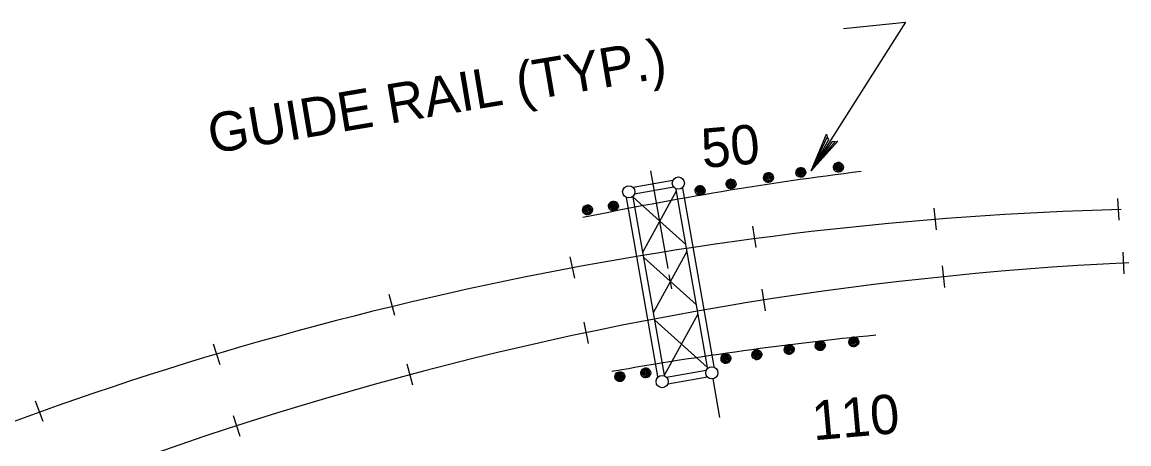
# Model space of a CAD drawing. Extents: x 36 to 2622, y -5330 to 219.
# Drawn here: x 593.7 to 678.2, y -4850.5 to -4818.3 of the extents above; entities that cross this region are included whole.
import ezdxf

# ---------------------------------------------------------------- set-up
doc = ezdxf.new("R2010")
doc.units = 0
doc.layers.add('2', color=7, linetype='Continuous')
doc.layers.add('3', color=7, linetype='Continuous')

# ---------------------------------------------------------------- blocks, each defined once
blk = doc.blocks.new('RARROW')
at = {"layer": '3'}
blk.add_lwpolyline([(-2.2695, 0.285), (-2.184875, 0.12075), (0, 0), (-2.2695, 0.285), (-2.38575, 0.384625), (0, 0), (-2.183125, -0.108), (-2.262875, -0.2705), (0, 0), (-2.38575, -0.379125), (-2.262875, -0.2705)], dxfattribs=at)

msp = doc.modelspace()

# ---------------------------------------------------------------- linework, layer by layer
at = {"layer": '2'}
for p, q in [((641.695, -4829.641), (643.005, -4837.09)), ((643.382, -4830.375), (640.364, -4830.908)), ((642.253, -4845.307), (639.846, -4831.665)), ((642.762, -4845.217), (640.368, -4831.631)), ((640.368, -4831.631), (644.385, -4835.257)), ((643.474, -4830.887), (640.449, -4831.421)), ((641.111, -4835.836), (643.663, -4831.161)), ((646.038, -4844.637), (643.644, -4831.053)), ((646.55, -4844.547), (644.156, -4830.962)), ((663.31, -4832.48), (663.481, -4834.13)), ((677.45, -4833.406), (677.366, -4831.75)), ((649.745, -4835.488), (649.49, -4833.851)), ((641.918, -4840.435), (644.474, -4835.763)), ((677.853, -4837.487), (677.77, -4835.831)), ((635.54, -4836.187), (635.883, -4837.81)), ((641.177, -4836.231), (645.194, -4839.855)), ((643.093, -4837.577), (643.278, -4838.636)), ((663.955, -4836.886), (664.126, -4838.536)), ((622.168, -4840.678), (621.742, -4839.074)), ((650.471, -4840.304), (650.216, -4838.667)), ((642.762, -4845.217), (645.319, -4840.545)), ((636.588, -4841.167), (636.931, -4842.79)), ((642.022, -4841.015), (646.038, -4844.637)), ((608.291, -4842.831), (608.801, -4844.408)), ((623.539, -4845.985), (623.113, -4844.381)), ((645.937, -4844.851), (642.914, -4845.386)), ((646.026, -4845.363), (643.005, -4845.898)), ((646.434, -4845.504), (646.95, -4848.437)), ((595.336, -4848.747), (594.745, -4847.198)), ((609.824, -4848.3), (610.334, -4849.877))]:
    msp.add_line(p, q, dxfattribs=at)
for points in [[(656.417, -4818.784), (661.157, -4818.291), (653.95, -4829.637)], [(656.03, -4829.356), (655.961, -4829.341), (655.965, -4829.293), (656.038, -4829.277), (656.09, -4829.312), (656.082, -4829.395), (656.007, -4829.437), (655.924, -4829.406), (655.88, -4829.327), (655.909, -4829.241), (656.005, -4829.198), (656.096, -4829.21), (656.154, -4829.306), (656.152, -4829.418), (656.036, -4829.512), (655.907, -4829.493), (655.822, -4829.393), (655.82, -4829.231), (655.934, -4829.135), (656.086, -4829.123), (656.182, -4829.2), (656.231, -4829.331), (656.229, -4829.447), (656.15, -4829.557), (656.028, -4829.599), (655.901, -4829.591), (655.797, -4829.505), (655.73, -4829.37), (655.745, -4829.258), (655.824, -4829.119), (655.971, -4829.054), (656.157, -4829.071), (656.265, -4829.166), (656.3, -4829.293), (656.319, -4829.453), (656.24, -4829.58), (656.094, -4829.659), (655.953, -4829.689), (655.845, -4829.678), (655.745, -4829.607), (655.68, -4829.497), (655.655, -4829.387), (655.662, -4829.277), (655.701, -4829.166), (655.776, -4829.075), (655.878, -4829.012), (655.988, -4828.977), (656.09, -4828.981), (656.19, -4829.01), (656.277, -4829.071), (656.348, -4829.156), (656.398, -4829.26), (656.408, -4829.383), (656.39, -4829.474), (656.34, -4829.574), (656.265, -4829.649), (656.159, -4829.713), (656.044, -4829.734), (655.951, -4829.73), (655.861, -4829.701), (655.793, -4829.651)], [(650.694, -4830.14), (650.625, -4830.125), (650.63, -4830.078), (650.702, -4830.061), (650.754, -4830.096), (650.746, -4830.179), (650.671, -4830.221), (650.588, -4830.19), (650.544, -4830.111), (650.573, -4830.025), (650.669, -4829.982), (650.76, -4829.994), (650.819, -4830.09), (650.817, -4830.202), (650.7, -4830.296), (650.571, -4830.277), (650.486, -4830.177), (650.484, -4830.015), (650.598, -4829.919), (650.75, -4829.907), (650.846, -4829.984), (650.896, -4830.115), (650.894, -4830.231), (650.815, -4830.342), (650.692, -4830.383), (650.565, -4830.375), (650.461, -4830.29), (650.394, -4830.155), (650.409, -4830.042), (650.488, -4829.903), (650.636, -4829.838), (650.821, -4829.855), (650.929, -4829.951), (650.964, -4830.078), (650.983, -4830.238), (650.904, -4830.364), (650.759, -4830.444), (650.617, -4830.473), (650.509, -4830.462), (650.409, -4830.392), (650.345, -4830.281), (650.32, -4830.171), (650.326, -4830.061), (650.365, -4829.951), (650.44, -4829.859), (650.542, -4829.797), (650.652, -4829.761), (650.754, -4829.766), (650.854, -4829.794), (650.942, -4829.855), (651.012, -4829.94), (651.062, -4830.044), (651.072, -4830.167), (651.054, -4830.258), (651.004, -4830.358), (650.929, -4830.433), (650.823, -4830.498), (650.708, -4830.519), (650.615, -4830.514), (650.525, -4830.485), (650.457, -4830.435)], [(653.161, -4829.749), (653.092, -4829.734), (653.097, -4829.686), (653.169, -4829.67), (653.221, -4829.705), (653.213, -4829.788), (653.138, -4829.83), (653.055, -4829.799), (653.011, -4829.72), (653.04, -4829.634), (653.136, -4829.591), (653.228, -4829.603), (653.286, -4829.699), (653.284, -4829.811), (653.167, -4829.905), (653.038, -4829.886), (652.953, -4829.786), (652.951, -4829.624), (653.065, -4829.528), (653.217, -4829.516), (653.313, -4829.593), (653.363, -4829.724), (653.361, -4829.84), (653.282, -4829.951), (653.159, -4829.992), (653.032, -4829.984), (652.928, -4829.899), (652.861, -4829.763), (652.876, -4829.651), (652.955, -4829.512), (653.103, -4829.447), (653.288, -4829.464), (653.396, -4829.56), (653.432, -4829.686), (653.45, -4829.847), (653.371, -4829.974), (653.226, -4830.052), (653.084, -4830.082), (652.976, -4830.071), (652.876, -4830.001), (652.812, -4829.89), (652.787, -4829.78), (652.793, -4829.67), (652.832, -4829.56), (652.907, -4829.468), (653.009, -4829.406), (653.12, -4829.37), (653.221, -4829.374), (653.321, -4829.404), (653.409, -4829.464), (653.479, -4829.549), (653.529, -4829.653), (653.54, -4829.776), (653.521, -4829.867), (653.471, -4829.967), (653.396, -4830.042), (653.29, -4830.107), (653.176, -4830.127), (653.082, -4830.123), (652.993, -4830.094), (652.924, -4830.044)], [(645.469, -4831.128), (645.4, -4831.113), (645.404, -4831.066), (645.477, -4831.049), (645.529, -4831.084), (645.52, -4831.168), (645.446, -4831.209), (645.362, -4831.178), (645.319, -4831.099), (645.348, -4831.014), (645.443, -4830.97), (645.535, -4830.982), (645.593, -4831.078), (645.591, -4831.19), (645.475, -4831.284), (645.346, -4831.265), (645.26, -4831.165), (645.258, -4831.003), (645.373, -4830.908), (645.525, -4830.895), (645.62, -4830.972), (645.67, -4831.103), (645.668, -4831.22), (645.589, -4831.33), (645.466, -4831.371), (645.34, -4831.363), (645.236, -4831.278), (645.169, -4831.142), (645.183, -4831.03), (645.263, -4830.891), (645.41, -4830.826), (645.595, -4830.843), (645.703, -4830.939), (645.739, -4831.066), (645.758, -4831.226), (645.679, -4831.353), (645.533, -4831.432), (645.392, -4831.461), (645.283, -4831.45), (645.183, -4831.38), (645.119, -4831.269), (645.094, -4831.159), (645.1, -4831.049), (645.14, -4830.939), (645.215, -4830.847), (645.317, -4830.785), (645.427, -4830.749), (645.529, -4830.753), (645.629, -4830.783), (645.716, -4830.843), (645.787, -4830.928), (645.837, -4831.032), (645.847, -4831.155), (645.828, -4831.247), (645.778, -4831.346), (645.703, -4831.421), (645.597, -4831.486), (645.483, -4831.507), (645.389, -4831.502), (645.3, -4831.473), (645.231, -4831.423)], [(647.836, -4830.633), (647.767, -4830.618), (647.771, -4830.57), (647.844, -4830.554), (647.896, -4830.589), (647.888, -4830.672), (647.813, -4830.714), (647.73, -4830.683), (647.686, -4830.604), (647.715, -4830.519), (647.811, -4830.475), (647.902, -4830.487), (647.961, -4830.583), (647.958, -4830.695), (647.842, -4830.789), (647.713, -4830.77), (647.628, -4830.67), (647.626, -4830.508), (647.74, -4830.412), (647.892, -4830.4), (647.988, -4830.477), (648.038, -4830.608), (648.036, -4830.724), (647.956, -4830.835), (647.834, -4830.876), (647.707, -4830.868), (647.603, -4830.783), (647.536, -4830.648), (647.551, -4830.535), (647.63, -4830.396), (647.778, -4830.331), (647.963, -4830.348), (648.071, -4830.444), (648.106, -4830.57), (648.125, -4830.731), (648.046, -4830.858), (647.9, -4830.937), (647.759, -4830.966), (647.651, -4830.955), (647.551, -4830.885), (647.486, -4830.774), (647.461, -4830.664), (647.467, -4830.554), (647.507, -4830.444), (647.582, -4830.352), (647.684, -4830.29), (647.794, -4830.254), (647.896, -4830.258), (647.996, -4830.288), (648.083, -4830.348), (648.154, -4830.433), (648.204, -4830.537), (648.214, -4830.66), (648.196, -4830.752), (648.146, -4830.851), (648.071, -4830.926), (647.965, -4830.991), (647.85, -4831.012), (647.757, -4831.007), (647.667, -4830.978), (647.599, -4830.928)], [(636.881, -4832.607), (636.813, -4832.592), (636.817, -4832.545), (636.89, -4832.528), (636.942, -4832.563), (636.933, -4832.646), (636.859, -4832.688), (636.775, -4832.657), (636.732, -4832.578), (636.761, -4832.493), (636.856, -4832.449), (636.948, -4832.461), (637.006, -4832.557), (637.004, -4832.669), (636.888, -4832.763), (636.759, -4832.744), (636.673, -4832.645), (636.671, -4832.482), (636.786, -4832.387), (636.938, -4832.374), (637.033, -4832.451), (637.083, -4832.582), (637.081, -4832.699), (637.002, -4832.809), (636.879, -4832.85), (636.752, -4832.842), (636.648, -4832.757), (636.582, -4832.622), (636.596, -4832.509), (636.676, -4832.37), (636.823, -4832.305), (637.008, -4832.322), (637.116, -4832.418), (637.152, -4832.545), (637.171, -4832.705), (637.091, -4832.832), (636.946, -4832.911), (636.804, -4832.94), (636.696, -4832.929), (636.596, -4832.859), (636.532, -4832.748), (636.507, -4832.638), (636.513, -4832.528), (636.553, -4832.418), (636.628, -4832.326), (636.73, -4832.264), (636.84, -4832.228), (636.942, -4832.233), (637.042, -4832.262), (637.129, -4832.322), (637.2, -4832.407), (637.25, -4832.511), (637.26, -4832.634), (637.241, -4832.726), (637.191, -4832.825), (637.116, -4832.9), (637.01, -4832.965), (636.896, -4832.986), (636.802, -4832.981), (636.713, -4832.952), (636.644, -4832.902)], [(638.856, -4832.316), (638.787, -4832.301), (638.791, -4832.253), (638.864, -4832.237), (638.916, -4832.272), (638.908, -4832.355), (638.833, -4832.397), (638.749, -4832.366), (638.706, -4832.287), (638.735, -4832.201), (638.831, -4832.158), (638.922, -4832.17), (638.98, -4832.266), (638.978, -4832.378), (638.862, -4832.472), (638.733, -4832.453), (638.648, -4832.353), (638.645, -4832.191), (638.76, -4832.095), (638.912, -4832.083), (639.007, -4832.16), (639.057, -4832.291), (639.055, -4832.407), (638.976, -4832.517), (638.853, -4832.559), (638.726, -4832.551), (638.623, -4832.466), (638.556, -4832.33), (638.571, -4832.218), (638.649, -4832.079), (638.797, -4832.014), (638.982, -4832.031), (639.091, -4832.127), (639.126, -4832.253), (639.145, -4832.413), (639.066, -4832.54), (638.92, -4832.619), (638.779, -4832.649), (638.67, -4832.638), (638.571, -4832.568), (638.506, -4832.457), (638.481, -4832.347), (638.487, -4832.237), (638.527, -4832.127), (638.602, -4832.035), (638.704, -4831.972), (638.814, -4831.937), (638.916, -4831.941), (639.016, -4831.971), (639.103, -4832.031), (639.174, -4832.116), (639.224, -4832.22), (639.234, -4832.343), (639.215, -4832.434), (639.166, -4832.534), (639.091, -4832.609), (638.985, -4832.674), (638.87, -4832.694), (638.777, -4832.69), (638.687, -4832.661), (638.618, -4832.611)], [(654.64, -4842.967), (654.572, -4842.952), (654.576, -4842.904), (654.649, -4842.887), (654.701, -4842.923), (654.692, -4843.006), (654.617, -4843.048), (654.534, -4843.016), (654.49, -4842.937), (654.519, -4842.852), (654.615, -4842.808), (654.707, -4842.821), (654.765, -4842.917), (654.763, -4843.029), (654.646, -4843.123), (654.517, -4843.104), (654.432, -4843.004), (654.43, -4842.842), (654.544, -4842.746), (654.696, -4842.734), (654.792, -4842.81), (654.842, -4842.941), (654.84, -4843.058), (654.761, -4843.168), (654.638, -4843.21), (654.511, -4843.202), (654.407, -4843.116), (654.341, -4842.981), (654.355, -4842.869), (654.434, -4842.729), (654.582, -4842.665), (654.767, -4842.681), (654.875, -4842.777), (654.911, -4842.904), (654.929, -4843.064), (654.85, -4843.191), (654.705, -4843.27), (654.563, -4843.299), (654.455, -4843.289), (654.355, -4843.218), (654.291, -4843.108), (654.266, -4842.998), (654.272, -4842.887), (654.312, -4842.777), (654.386, -4842.686), (654.488, -4842.623), (654.599, -4842.588), (654.701, -4842.592), (654.8, -4842.621), (654.888, -4842.681), (654.958, -4842.767), (655.008, -4842.871), (655.019, -4842.994), (655, -4843.085), (654.95, -4843.185), (654.875, -4843.26), (654.769, -4843.324), (654.655, -4843.345), (654.561, -4843.341), (654.472, -4843.312), (654.403, -4843.262)], [(657.207, -4842.673), (657.139, -4842.659), (657.143, -4842.611), (657.215, -4842.594), (657.267, -4842.63), (657.259, -4842.713), (657.184, -4842.754), (657.101, -4842.723), (657.057, -4842.644), (657.087, -4842.559), (657.182, -4842.515), (657.274, -4842.528), (657.332, -4842.623), (657.33, -4842.735), (657.213, -4842.829), (657.084, -4842.81), (656.999, -4842.711), (656.997, -4842.548), (657.111, -4842.453), (657.263, -4842.44), (657.359, -4842.517), (657.409, -4842.648), (657.407, -4842.765), (657.328, -4842.875), (657.205, -4842.917), (657.078, -4842.908), (656.974, -4842.823), (656.908, -4842.688), (656.922, -4842.575), (657.001, -4842.436), (657.149, -4842.372), (657.334, -4842.388), (657.442, -4842.484), (657.477, -4842.611), (657.496, -4842.771), (657.417, -4842.898), (657.272, -4842.977), (657.13, -4843.006), (657.022, -4842.996), (656.922, -4842.925), (656.858, -4842.815), (656.833, -4842.704), (656.839, -4842.594), (656.878, -4842.484), (656.953, -4842.392), (657.055, -4842.33), (657.166, -4842.294), (657.267, -4842.299), (657.367, -4842.328), (657.455, -4842.388), (657.525, -4842.473), (657.575, -4842.578), (657.586, -4842.7), (657.567, -4842.792), (657.517, -4842.891), (657.442, -4842.967), (657.336, -4843.031), (657.222, -4843.052), (657.128, -4843.048), (657.039, -4843.019), (656.97, -4842.968)], [(649.808, -4843.661), (649.739, -4843.647), (649.743, -4843.599), (649.816, -4843.582), (649.868, -4843.618), (649.86, -4843.701), (649.785, -4843.742), (649.702, -4843.711), (649.658, -4843.632), (649.687, -4843.547), (649.783, -4843.503), (649.874, -4843.516), (649.933, -4843.611), (649.931, -4843.724), (649.814, -4843.817), (649.685, -4843.798), (649.6, -4843.699), (649.598, -4843.536), (649.712, -4843.441), (649.864, -4843.428), (649.96, -4843.505), (650.01, -4843.636), (650.008, -4843.753), (649.928, -4843.863), (649.806, -4843.905), (649.679, -4843.896), (649.575, -4843.811), (649.508, -4843.676), (649.523, -4843.564), (649.602, -4843.424), (649.75, -4843.36), (649.935, -4843.376), (650.043, -4843.472), (650.078, -4843.599), (650.097, -4843.759), (650.018, -4843.886), (649.872, -4843.965), (649.731, -4843.994), (649.623, -4843.984), (649.523, -4843.913), (649.458, -4843.803), (649.433, -4843.692), (649.44, -4843.582), (649.479, -4843.472), (649.554, -4843.38), (649.656, -4843.318), (649.766, -4843.283), (649.868, -4843.287), (649.968, -4843.316), (650.055, -4843.376), (650.126, -4843.462), (650.176, -4843.565), (650.186, -4843.688), (650.168, -4843.78), (650.118, -4843.88), (650.043, -4843.954), (649.937, -4844.019), (649.822, -4844.04), (649.729, -4844.036), (649.639, -4844.007), (649.571, -4843.957)], [(652.275, -4843.258), (652.206, -4843.243), (652.21, -4843.195), (652.283, -4843.179), (652.335, -4843.214), (652.327, -4843.297), (652.252, -4843.339), (652.169, -4843.308), (652.125, -4843.229), (652.154, -4843.143), (652.25, -4843.1), (652.341, -4843.112), (652.4, -4843.208), (652.398, -4843.32), (652.281, -4843.414), (652.152, -4843.395), (652.067, -4843.295), (652.065, -4843.133), (652.179, -4843.037), (652.331, -4843.025), (652.427, -4843.102), (652.477, -4843.233), (652.475, -4843.349), (652.396, -4843.459), (652.273, -4843.501), (652.146, -4843.493), (652.042, -4843.408), (651.975, -4843.272), (651.99, -4843.16), (652.069, -4843.021), (652.217, -4842.956), (652.402, -4842.973), (652.51, -4843.068), (652.545, -4843.195), (652.564, -4843.355), (652.485, -4843.482), (652.339, -4843.561), (652.198, -4843.591), (652.09, -4843.58), (651.99, -4843.509), (651.926, -4843.399), (651.9, -4843.289), (651.907, -4843.179), (651.946, -4843.068), (652.021, -4842.977), (652.123, -4842.914), (652.233, -4842.879), (652.335, -4842.883), (652.435, -4842.912), (652.523, -4842.973), (652.593, -4843.058), (652.643, -4843.162), (652.654, -4843.285), (652.635, -4843.376), (652.585, -4843.476), (652.51, -4843.551), (652.404, -4843.615), (652.289, -4843.636), (652.196, -4843.632), (652.106, -4843.603), (652.038, -4843.553)], [(647.443, -4843.953), (647.374, -4843.938), (647.378, -4843.89), (647.451, -4843.873), (647.503, -4843.909), (647.495, -4843.992), (647.42, -4844.034), (647.337, -4844.002), (647.293, -4843.923), (647.322, -4843.838), (647.418, -4843.794), (647.509, -4843.807), (647.567, -4843.903), (647.565, -4844.015), (647.449, -4844.109), (647.32, -4844.09), (647.235, -4843.99), (647.232, -4843.828), (647.347, -4843.732), (647.499, -4843.72), (647.595, -4843.797), (647.644, -4843.927), (647.642, -4844.044), (647.563, -4844.154), (647.441, -4844.196), (647.314, -4844.188), (647.21, -4844.102), (647.143, -4843.967), (647.158, -4843.855), (647.237, -4843.715), (647.384, -4843.651), (647.57, -4843.668), (647.678, -4843.763), (647.713, -4843.89), (647.732, -4844.05), (647.653, -4844.177), (647.507, -4844.256), (647.366, -4844.285), (647.258, -4844.275), (647.158, -4844.204), (647.093, -4844.094), (647.068, -4843.984), (647.074, -4843.873), (647.114, -4843.763), (647.189, -4843.672), (647.291, -4843.609), (647.401, -4843.574), (647.503, -4843.578), (647.603, -4843.607), (647.69, -4843.668), (647.761, -4843.753), (647.811, -4843.857), (647.821, -4843.98), (647.803, -4844.071), (647.753, -4844.171), (647.678, -4844.246), (647.572, -4844.31), (647.457, -4844.331), (647.364, -4844.327), (647.274, -4844.298), (647.206, -4844.248)], [(639.349, -4845.332), (639.28, -4845.317), (639.284, -4845.269), (639.357, -4845.253), (639.409, -4845.288), (639.4, -4845.371), (639.326, -4845.413), (639.242, -4845.382), (639.199, -4845.302), (639.228, -4845.217), (639.323, -4845.173), (639.415, -4845.186), (639.473, -4845.282), (639.471, -4845.394), (639.355, -4845.488), (639.226, -4845.469), (639.14, -4845.369), (639.138, -4845.207), (639.253, -4845.111), (639.405, -4845.099), (639.5, -4845.176), (639.55, -4845.307), (639.548, -4845.423), (639.469, -4845.533), (639.346, -4845.575), (639.22, -4845.567), (639.115, -4845.481), (639.049, -4845.346), (639.063, -4845.234), (639.143, -4845.095), (639.29, -4845.03), (639.475, -4845.047), (639.584, -4845.142), (639.619, -4845.269), (639.638, -4845.429), (639.559, -4845.556), (639.413, -4845.635), (639.272, -4845.664), (639.163, -4845.654), (639.063, -4845.583), (638.999, -4845.473), (638.974, -4845.363), (638.98, -4845.253), (639.02, -4845.142), (639.095, -4845.051), (639.197, -4844.988), (639.307, -4844.953), (639.409, -4844.957), (639.509, -4844.986), (639.596, -4845.047), (639.667, -4845.132), (639.717, -4845.236), (639.727, -4845.359), (639.708, -4845.45), (639.659, -4845.55), (639.584, -4845.625), (639.477, -4845.689), (639.363, -4845.71), (639.269, -4845.706), (639.18, -4845.677), (639.111, -4845.627)], [(641.323, -4845.04), (641.254, -4845.026), (641.258, -4844.978), (641.331, -4844.961), (641.383, -4844.997), (641.375, -4845.08), (641.3, -4845.122), (641.216, -4845.09), (641.173, -4845.011), (641.202, -4844.926), (641.298, -4844.882), (641.389, -4844.895), (641.447, -4844.99), (641.445, -4845.103), (641.329, -4845.196), (641.2, -4845.178), (641.115, -4845.078), (641.113, -4844.916), (641.227, -4844.82), (641.379, -4844.807), (641.475, -4844.884), (641.524, -4845.016), (641.522, -4845.132), (641.443, -4845.242), (641.321, -4845.284), (641.194, -4845.275), (641.09, -4845.19), (641.023, -4845.055), (641.038, -4844.943), (641.117, -4844.803), (641.264, -4844.739), (641.45, -4844.755), (641.558, -4844.851), (641.593, -4844.978), (641.612, -4845.138), (641.533, -4845.265), (641.387, -4845.344), (641.246, -4845.373), (641.138, -4845.363), (641.038, -4845.292), (640.973, -4845.182), (640.948, -4845.072), (640.954, -4844.961), (640.994, -4844.851), (641.069, -4844.76), (641.171, -4844.697), (641.281, -4844.662), (641.383, -4844.666), (641.483, -4844.695), (641.57, -4844.755), (641.641, -4844.841), (641.691, -4844.945), (641.701, -4845.068), (641.683, -4845.159), (641.633, -4845.259), (641.558, -4845.334), (641.452, -4845.398), (641.337, -4845.419), (641.244, -4845.415), (641.154, -4845.386), (641.086, -4845.336)]]:
    msp.add_lwpolyline(points, dxfattribs=at)
for centre in [(640.023, -4831.232), (643.811, -4830.564), (646.365, -4845.042), (642.577, -4845.71)]:
    msp.add_circle(centre, 0.467, dxfattribs=at)
for centre, radius, start, end in [((690.687, -5094.225), 266.583, 97.09131, 101.72382), ((684.767, -5099.067), 266.583, 91.53624, 111.91461), ((690.906, -5098.772), 262.439, 92.77437, 119.99972), ((685.17, -5107.453), 266.583, 95.65915, 100.02902)]:
    msp.add_arc(centre, radius, start, end, dxfattribs=at)

# ---------------------------------------------------------------- block references
at = {"layer": '2', "xscale": 1.257434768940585, "yscale": 1.3092961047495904, "rotation": -122.17524514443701}
msp.add_blockref('RARROW', (653.95, -4829.636), dxfattribs=at)

# ---------------------------------------------------------------- texts
at = {"layer": '2'}
for s, rotation, p in [('GUIDE RAIL (TYP.)', 9.52662, (608.174, -4828.33)), ('50', 5, (645.693, -4829.424)), ('110', 5, (654.139, -4850.193))]:
    msp.add_text(s, height=2.9955, rotation=rotation, dxfattribs=at).set_placement(p)

doc.saveas('drawing.dxf')
